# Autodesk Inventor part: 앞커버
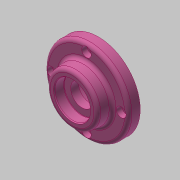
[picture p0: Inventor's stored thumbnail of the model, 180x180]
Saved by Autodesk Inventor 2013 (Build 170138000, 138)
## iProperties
Created: 2017-08
Part Number: 앞커버
Material: 알루미늄 6061
Document SubType Name: Modeling
Designer: mduedu
Density: 2.71 g/cm^3
Mass: 117.255 g
Surface Area: 148.119 cm^2
Volume: 43.2674 cm^3
Author: mduedu
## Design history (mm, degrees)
sketch "스케치1"
  geometry: C1 r 35 at (0, 0); 1 further point
  constraints: 1 centre point, 1 coincident
  dimensions: "d0" = 70 diameter of C1
extrude "돌출1" new body sketch "스케치1" distance "d1" = 10; taper "d2" = 0 deg
sketch "스케치2"
  geometry: C1 r 22 at (0, 0); 1 further point
  constraints: 1 centre point, 1 coincident
  dimensions: "d3" = 44 diameter of C1
node "작업 평면1"
sketch "스케치3"
  geometry: C1 r 21 at (0, 0); 1 further point
  constraints: 1 centre point, 1 coincident
  dimensions: "d5" = 42 diameter of C1
feature "로프트1" sketch "스케치3" dims "d6" = 0, "d7" = 90 deg, "d8" = 0, "d9" = 90 deg
sketch "스케치4"
  geometry: C1 r 24 at (0, 0); 1 further point
  constraints: 1 centre point, 1 coincident
  dimensions: "d86" = 48 diameter of C1
extrude "돌출2" join sketch "스케치4" distance "d10" = 8; taper "d11" = 0 deg
hole "구멍1" diameter "d14" = 40; stored, may be unused: countersink angle "d18" = 90 deg, drill point angle "d20" = 0 deg; dims "d15" = 6, "d16" = 4, "d17" = 2, "d19" = 12, "d87" = 10, "d88" = 10
hole "구멍2" diameter "d23" = 34; stored, may be unused: countersink angle "d27" = 90 deg, drill point angle "d29" = 0 deg; dims "d21" = 10, "d22" = 10, "d24" = 6, "d25" = 4, "d26" = 2, "d28" = 3
hole "구멍3" diameter "d32" = 19; stored, may be unused: countersink angle "d36" = 90 deg, drill point angle "d38" = 0 deg; dims "d30" = 10, "d31" = 10, "d33" = 6, "d34" = 4, "d35" = 2, "d37" = 3
chamfer "모따기1" distance "d39" = 1; stored, may be unused: second distance "d40" = 2, angle "d41" = 45 deg
sketch "스케치5"
  geometry: C1 r 15 at (0, 0); 1 further point
  constraints: 1 centre point, 1 coincident
  dimensions: "d42" = 30 diameter of C1
extrude "돌출3" cut sketch "스케치5" distance "d43" = 8.3; taper "d44" = 0 deg
chamfer "모따기2" distance "d47" = 0.8; stored, may be unused: second distance "d48" = 2, angle "d49" = 30 deg
fillet "모깎기1" dims "d50" = 0.3
fillet "모깎기2" dims "d51" = 0.3
fillet "모깎기3" dims "d52" = 3
sketch "스케치6" dims "d53" = 58
  geometry: 6 further points
  constraints: 2 vertical alignment, 1 coincident, 7 other
  dimensions: "d56" = 360 deg dimension on point (0, 0) point (0, 29) (derived)
sketch "스케치9" dims "d85" = 58 (derived)
  geometry: 6 further points
  constraints: 1 coincident, 1 vertical alignment, 6 other
hole "구멍6" sketch "스케치9" at (-29, 0), (0, -29), (29, 0), (0, 29) diameter "d72" = 4.5; stored, may be unused: countersink angle "d76" = 90 deg, drill point angle "d78" = 0 deg; dims "d73" = 6, "d74" = 8, "d75" = 4.6, "d77" = 8
fillet "모깎기4" dims "d79" = 3
fillet "모깎기5" dims "d80" = 3
fillet "모깎기6" dims "d81" = 3
node "솔리드1"
other parameters: "d4" = 12
